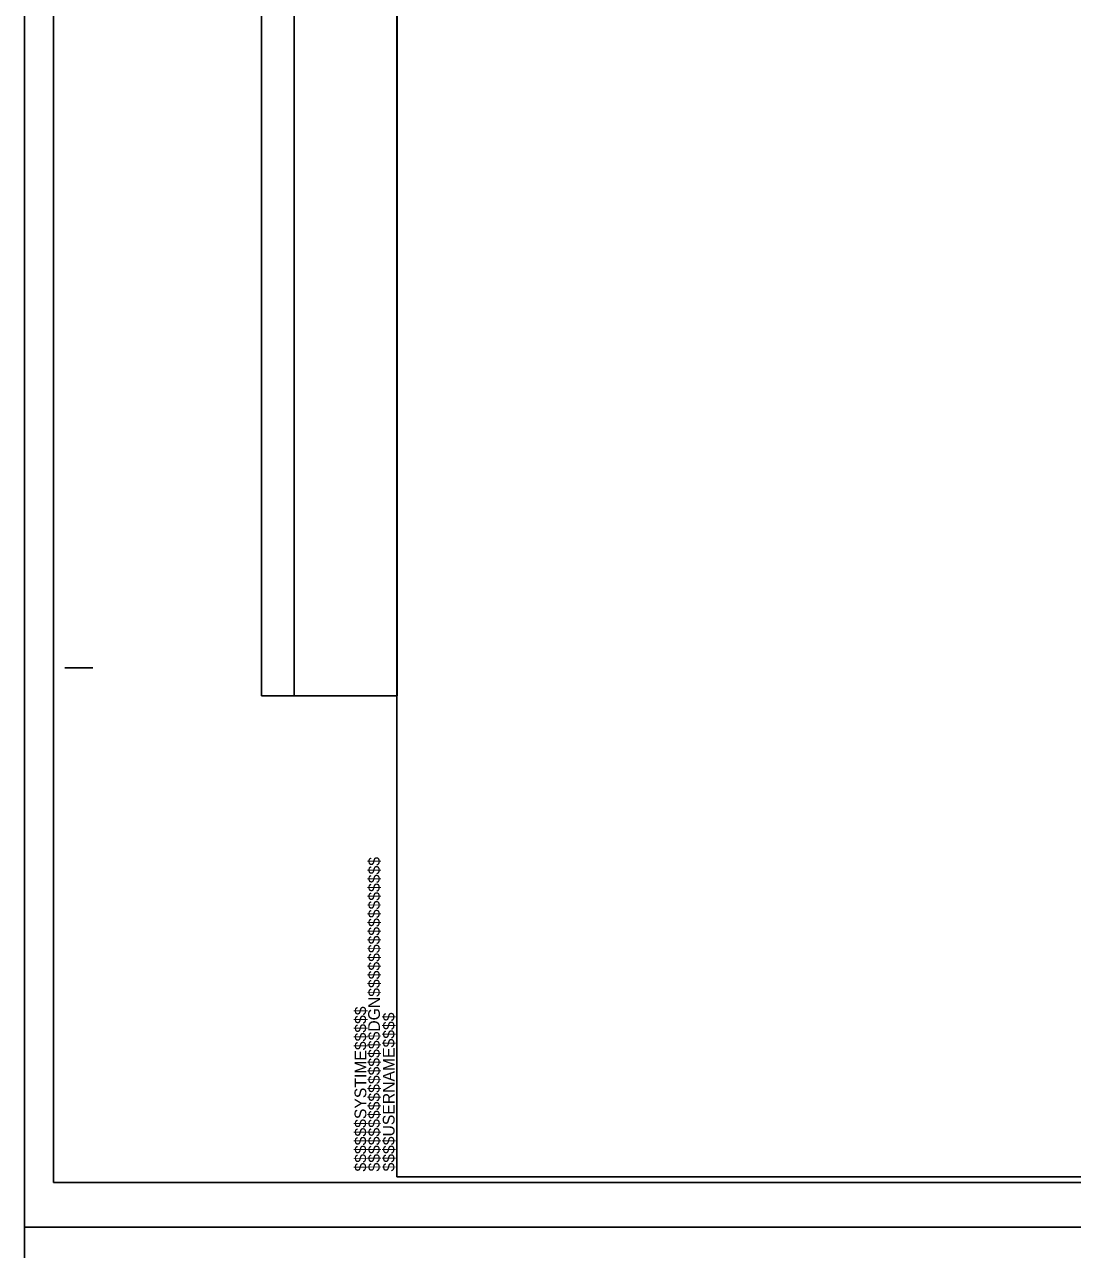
# Model space of a CAD drawing. Extents: x 2241081 to 2251104, y 658534 to 663427.
# Drawn here: x 2247636 to 2248104, y 660714 to 661262 of the extents above; entities that cross this region are included whole.
import ezdxf

# ---------------------------------------------------------------- set-up
doc = ezdxf.new("R2010")
doc.units = 0
for name, color, linetype in [('Sheet Block Revision CELL', 7, 'Continuous'), ('Sheet Cutting Line CELL', 7, 'Continuous'), ('Sheet Plan CELL', 7, 'Continuous'), ('Sheet Plot Border Inside CELL', 7, 'Continuous'), ('Sheet Plot Border Outside CELL', 7, 'Continuous')]:
    doc.layers.add(name, color=color, linetype=linetype)

msp = doc.modelspace()

# ---------------------------------------------------------------- linework, layer by layer
at = {"layer": 'Sheet Block Revision CELL'}
msp.add_line((2247756.02, 660961.78), (2247756.01, 661752.42), dxfattribs=at)
msp.add_lwpolyline([(2247741.47, 660961.75), (2247741.47, 661752.4), (2247802.01, 661752.43), (2247802.01, 660961.78)], close=True, dxfattribs=at)
at = {"layer": 'Sheet Cutting Line CELL'}
for p, q in [((2247635.51, 661819.27), (2247635.51, 660724.27)), ((2247635.51, 660724.27), (2249319.01, 660724.26)), ((2249319.01, 660724.26), (2247635.51, 660724.27)), ((2247635.51, 660724.27), (2247635.51, 659629.27))]:
    msp.add_line(p, q, dxfattribs=at)
at = {"layer": 'Sheet Plan CELL'}
for p, q in [((2247653.52, 660974.27), (2247666.02, 660974.25)), ((2247801.99, 660746.78), (2247801.99, 660746.78))]:
    msp.add_line(p, q, dxfattribs=at)
for points in [[(2247801.99, 660746.78), (2247801.97, 661796.75), (2249101.96, 661796.79), (2249101.97, 661646.73), (2249302.01, 661646.71), (2249302.01, 660746.78)], [(2249302.03, 661796.78), (2247802, 661796.78), (2247801.99, 660746.78), (2249302.01, 660746.78)]]:
    msp.add_lwpolyline(points, close=True, dxfattribs=at)
at = {"layer": 'Sheet Plot Border Inside CELL'}
msp.add_lwpolyline([(2247648.51, 660744.27), (2249314.49, 660744.28), (2249314.51, 661799.26), (2247648.51, 661799.27)], close=True, dxfattribs=at)
at = {"layer": 'Sheet Plot Border Outside CELL'}
for points in [[(2247635.51, 660724.27), (2249319.01, 660724.26), (2249319.01, 661819.26), (2247635.51, 661819.27)], [(2247635.51, 659629.27), (2249319.01, 659629.26), (2249319.01, 660724.26), (2247635.51, 660724.27)]]:
    msp.add_lwpolyline(points, close=True, dxfattribs=at)

# ---------------------------------------------------------------- texts
at = {"layer": 'Sheet Plan CELL'}
for s, p in [('$$$$$$$$$$$$$$$$DGN$$$$$$$$$$$$$$$$', (2247794.36, 660749.14)), ('$$$$$$SYSTIME$$$$$', (2247788.28, 660749.12)), ('$$$$USERNAME$$$$', (2247800.91, 660749.15))]:
    msp.add_text(s, height=5.25, rotation=89.9999, dxfattribs=at).set_placement(p)

doc.saveas('drawing.dxf')
